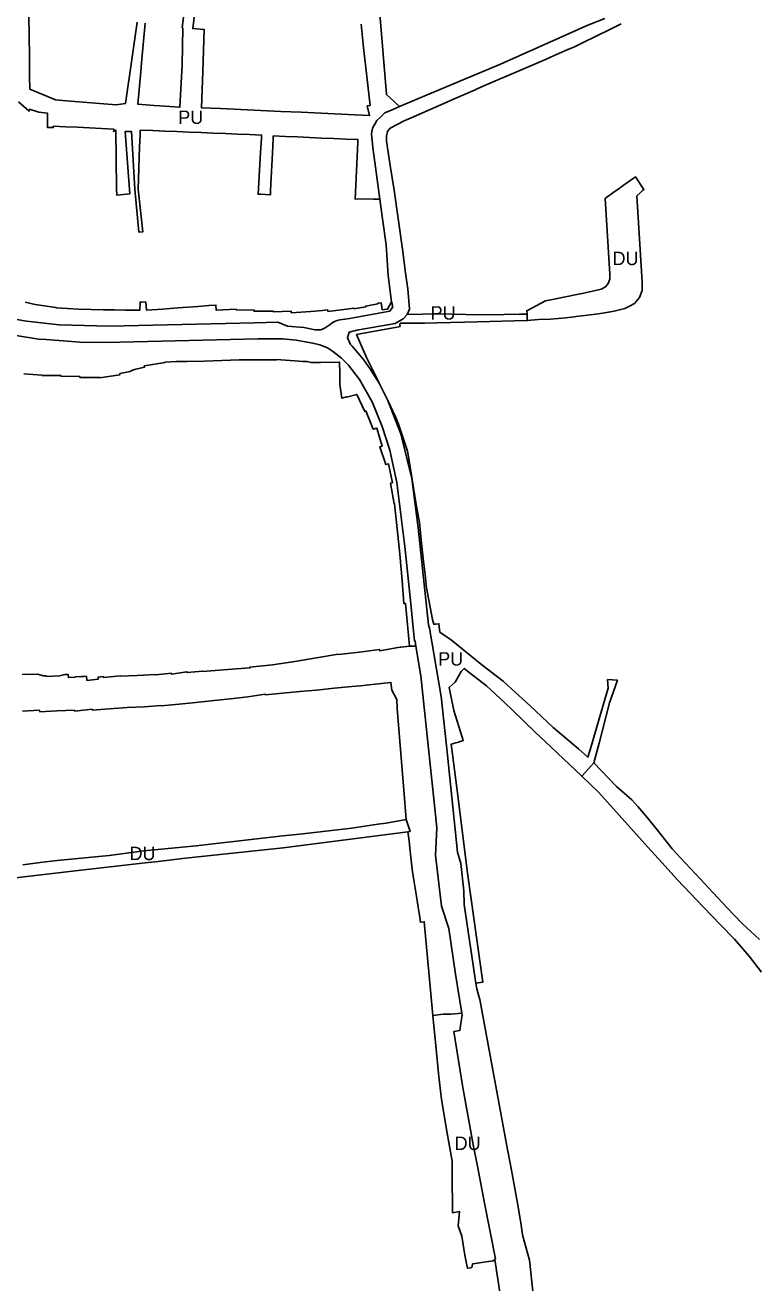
# Model space of a CAD drawing. Extents: x -521047 to -518054, y -1194945 to -1189555.
# Drawn here: x -519578 to -519036, y -1192557 to -1191621 of the extents above; entities that cross this region are included whole.
import ezdxf

# ---------------------------------------------------------------- set-up
doc = ezdxf.new("R2010")
doc.units = 0
for name, color, linetype in [('90310013', 7, 'Continuous'), ('90320013', 7, 'Continuous'), ('90450013', 7, 'Continuous')]:
    doc.layers.add(name, color=color, linetype=linetype)

msp = doc.modelspace()

# ---------------------------------------------------------------- linework, layer by layer
at = {"layer": '90310013'}
for points in [[(-519204.45, -1191836.01), (-519204.44, -1191840.74), (-519196.06, -1191840.09), (-519187.09, -1191839.8), (-519175.58, -1191838.62), (-519169.59, -1191838.01), (-519167.92, -1191837.84), (-519159.65, -1191836.74), (-519151.39, -1191835.65), (-519148.46, -1191835.26), (-519144.03, -1191834.48), (-519139.61, -1191833.71), (-519138.79, -1191833.51), (-519135.64, -1191832.73), (-519131.67, -1191831.75), (-519128.2, -1191830.17), (-519124.71, -1191827.98), (-519120.84, -1191823.71), (-519118.96, -1191818.4), (-519118.77, -1191812.14), (-519122.77, -1191748), (-519120.3, -1191745.63), (-519118.66, -1191744.06), (-519117.54, -1191743.31), (-519123.94, -1191733.72), (-519133.08, -1191740.22), (-519137.83, -1191743.66), (-519139.7, -1191745.02), (-519146.33, -1191749.83), (-519142.86, -1191806.26), (-519142.91, -1191809.87), (-519144.27, -1191813.29), (-519146.16, -1191815.78), (-519148.84, -1191817.18), (-519149.29, -1191817.29), (-519154.61, -1191818.54), (-519158.11, -1191819.36), (-519160.39, -1191819.9), (-519162.27, -1191820.28), (-519166.23, -1191821.08), (-519186.83, -1191825.25), (-519190.77, -1191826.05), (-519204.81, -1191833.46), (-519204.45, -1191836.01)], [(-519031.55, -1192301.49), (-519044.36, -1192289.47), (-519055.66, -1192277.84), (-519066.07, -1192266.75), (-519075.61, -1192256.39), (-519086.83, -1192244.28), (-519096.48, -1192233.98), (-519107.53, -1192220.17), (-519116.18, -1192209.51), (-519122, -1192202.34), (-519126.58, -1192197.51), (-519137.98, -1192187.52), (-519154.78, -1192169.89), (-519163.86, -1192179.96), (-519151.64, -1192191.56), (-519140.2, -1192204.21), (-519114.65, -1192232.63), (-519104.36, -1192244.08), (-519092.95, -1192256.78), (-519073.17, -1192277.32), (-519060.48, -1192290.5), (-519050.21, -1192301.17), (-519039.22, -1192313.8), (-519030.1, -1192325.84)], [(-519293.15, -1192221.23), (-519291.45, -1192221.01), (-519294.58, -1192212.21), (-519309.5, -1192214.8), (-519315.51, -1192215.67), (-519322.01, -1192216.62), (-519334.91, -1192218.48), (-519347.79, -1192219.96), (-519360.66, -1192221.43), (-519373.52, -1192222.91), (-519386.39, -1192224.39), (-519399.25, -1192225.86), (-519412.12, -1192227.34), (-519425.05, -1192228.82), (-519438.08, -1192230.21), (-519450.83, -1192231.68), (-519463.7, -1192232.94), (-519476.84, -1192234.28), (-519489.62, -1192235.55), (-519502.68, -1192237.21), (-519515.54, -1192238.85), (-519528.34, -1192240.22), (-519541.4, -1192241.29), (-519554.2, -1192242.66), (-519566.88, -1192244.15), (-519579.82, -1192245.81)], [(-519608.83, -1192258.36), (-519538.54, -1192250.02), (-519486.4, -1192244.11), (-519478.96, -1192243.26), (-519458.84, -1192240.98), (-519385.99, -1192233.14), (-519293.15, -1192221.23)], [(-519274.55, -1192357.98), (-519272, -1192385.55), (-519270.57, -1192401.05), (-519268.72, -1192416.34), (-519268.03, -1192422.01), (-519263.91, -1192445.66), (-519260.27, -1192466.51), (-519260.21, -1192475.38), (-519260.01, -1192504.83), (-519254.84, -1192503.78), (-519255.72, -1192514.6), (-519253.11, -1192522.25), (-519250.78, -1192536.34), (-519249.45, -1192543.81), (-519248.82, -1192546.17), (-519246.64, -1192545.7), (-519245.6, -1192545.49), (-519245.21, -1192542.95), (-519244.62, -1192542.72), (-519233.52, -1192541.1), (-519233.01, -1192541.03), (-519229.85, -1192540.57), (-519228.6, -1192539.54), (-519227.98, -1192539.02), (-519236.13, -1192497.59), (-519241.55, -1192470.11), (-519244.42, -1192455.6), (-519252.35, -1192411.52), (-519258.95, -1192369.88), (-519254.68, -1192369.2), (-519252.85, -1192357.24), (-519252.99, -1192356.37), (-519261, -1192356.96), (-519266.9, -1192356.98), (-519274.55, -1192357.98)]]:
    msp.add_lwpolyline(points, dxfattribs=at)
at = {"layer": '90320013'}
for points in [[(-519146.78, -1191615.88), (-519159.42, -1191620.98), (-519166.49, -1191624.15), (-519224.33, -1191649.88), (-519275.99, -1191671.57), (-519285.21, -1191675.48), (-519299.42, -1191681.52), (-519304.96, -1191683.89), (-519310.5, -1191686.25), (-519313.44, -1191689.04), (-519316.37, -1191691.83), (-519317.94, -1191694.71), (-519319.51, -1191697.58), (-519320.32, -1191701.75), (-519319.42, -1191711.86), (-519314, -1191750.49), (-519312.01, -1191764.97), (-519309.33, -1191784.48), (-519307.98, -1191807.22), (-519305.47, -1191826.76), (-519304.48, -1191830.56), (-519306.68, -1191833.7), (-519336.74, -1191839.11), (-519339.91, -1191839.62), (-519343.88, -1191840.31), (-519345.85, -1191840.71), (-519348.24, -1191841.65), (-519349.53, -1191842.44), (-519351.15, -1191843.6), (-519354.1, -1191845.76), (-519355.34, -1191846.53), (-519356.3, -1191846.96), (-519357.24, -1191847.32), (-519358.25, -1191847.56), (-519359.26, -1191847.67), (-519360.3, -1191847.76), (-519362.28, -1191847.68), (-519370.7, -1191846.05), (-519382.85, -1191844.82), (-519389.94, -1191842.05), (-519407.35, -1191842.43), (-519515.39, -1191844.88), (-519552.85, -1191843.86), (-519577.08, -1191841.18), (-519613.12, -1191835.08)], [(-519196.54, -1192598), (-519202.8, -1192540.04), (-519207.76, -1192522.22), (-519207.97, -1192520.87), (-519209.28, -1192512.28), (-519210.61, -1192503.54), (-519211.21, -1192500.28), (-519215.75, -1192475.83), (-519217.2, -1192467.98), (-519219.07, -1192457.81), (-519239.61, -1192346.18), (-519240.39, -1192343.49), (-519241.97, -1192338.08), (-519242.61, -1192333.86), (-519251.47, -1192275.39), (-519251.5, -1192265.15), (-519253.85, -1192244.78), (-519256.4, -1192236.48), (-519263.74, -1192164.26), (-519264.49, -1192157.17), (-519268.4, -1192120.48), (-519277.03, -1192069.78), (-519277.9, -1192067.2), (-519285.48, -1191994.93), (-519290.34, -1191958.3), (-519298.51, -1191925.1), (-519308.18, -1191900.28), (-519308.65, -1191899.33), (-519312.08, -1191892.37), (-519314.56, -1191887.33), (-519321, -1191877.16), (-519326.18, -1191869.79), (-519334.75, -1191859.93), (-519335.92, -1191858.58), (-519338.25, -1191853.54), (-519337.02, -1191849.51), (-519331.33, -1191847.96), (-519302.69, -1191842.95), (-519296.63, -1191839.59), (-519293.72, -1191836.26), (-519292.11, -1191832.38), (-519293.33, -1191817.07), (-519294.73, -1191807.26), (-519297.34, -1191787.75), (-519300.4, -1191764.9), (-519303.36, -1191743.79), (-519306.5, -1191725.42), (-519309.15, -1191707.14), (-519309.22, -1191703.48), (-519308.36, -1191700.15), (-519306.43, -1191697.63), (-519296.03, -1191692.09), (-519290.75, -1191689.81), (-519268.59, -1191680.16), (-519259.22, -1191676.08), (-519243.58, -1191669.19), (-519241.68, -1191668.36), (-519236.65, -1191666.15), (-519233.12, -1191664.6), (-519228.08, -1191662.46), (-519209.86, -1191654.59), (-519190.89, -1191646.39), (-519187.15, -1191644.77), (-519182.56, -1191642.78), (-519174.11, -1191639.14), (-519171.02, -1191637.8), (-519169.3, -1191636.96), (-519163.4, -1191634.08), (-519142.94, -1191624.08), (-519134.57, -1191619.98)], [(-519615.32, -1191846.99), (-519568.13, -1191854.57), (-519562.35, -1191854.98), (-519534.11, -1191856.98), (-519507.57, -1191856.77), (-519404.6, -1191854.48), (-519386.65, -1191854.46), (-519376.26, -1191855.26), (-519363.89, -1191857.47), (-519358.75, -1191858.92), (-519357.45, -1191859.28), (-519352.97, -1191861.17), (-519349.45, -1191863.46), (-519342.53, -1191868.86), (-519337.41, -1191873.89), (-519329.28, -1191884.7), (-519319.74, -1191901.29), (-519312.31, -1191919.57), (-519306.61, -1191937.19), (-519301.58, -1191961.19), (-519295.55, -1192009.01), (-519291.37, -1192049.22), (-519288.24, -1192079.39), (-519287.79, -1192079.36), (-519287.33, -1192083.23), (-519283.62, -1192105.11), (-519272.72, -1192208.59), (-519271.7, -1192218.25), (-519272.76, -1192238.61), (-519268.16, -1192276.7), (-519262.65, -1192293.24), (-519257.69, -1192327.13), (-519252.99, -1192356.37), (-519252.85, -1192357.24), (-519254.68, -1192369.2), (-519258.95, -1192369.88), (-519252.35, -1192411.52), (-519244.42, -1192455.6), (-519241.55, -1192470.11), (-519236.13, -1192497.59), (-519227.98, -1192539.02), (-519228.6, -1192539.54), (-519220.59, -1192591.78)]]:
    msp.add_lwpolyline(points, dxfattribs=at)
at = {"layer": '90450013'}
for points in [[(-519582.88, -1191677.87), (-519574.98, -1191684.89), (-519574.85, -1191683.54), (-519567.78, -1191685.68), (-519561.34, -1191686.44), (-519561.51, -1191696.96), (-519561.2, -1191697), (-519557.19, -1191697.14), (-519557.14, -1191696.09), (-519547.97, -1191696.52), (-519539.14, -1191696.94), (-519530.15, -1191697.36), (-519521.15, -1191697.78), (-519512.12, -1191698.2), (-519512.16, -1191699.05), (-519512.2, -1191700.05), (-519510.53, -1191699.1), (-519510.01, -1191742.32), (-519510.01, -1191742.53), (-519509.74, -1191747.47), (-519500.23, -1191746.39), (-519500.5, -1191743.31), (-519503.66, -1191700.1), (-519498.91, -1191700.04), (-519496.38, -1191742.87), (-519493.35, -1191774.96), (-519490.37, -1191774.64), (-519493.88, -1191742.97), (-519492.93, -1191711.67), (-519492.48, -1191702.17), (-519492.41, -1191700.03), (-519492.37, -1191699), (-519483.09, -1191699.39), (-519474.12, -1191699.76), (-519465.11, -1191700.14), (-519456.16, -1191700.51), (-519447.05, -1191700.89), (-519438.15, -1191701.26), (-519429.07, -1191701.64), (-519420.12, -1191702.01), (-519411.16, -1191702.39), (-519402.09, -1191702.77), (-519402.22, -1191705.03), (-519402.82, -1191715.71), (-519404.65, -1191746.7), (-519402.92, -1191746.8), (-519395.58, -1191747.25), (-519395.4, -1191744.56), (-519395.12, -1191739.06), (-519394.09, -1191716.18), (-519393.5, -1191705.59), (-519393.39, -1191703.3), (-519384.38, -1191703.7), (-519375.45, -1191704.1), (-519366.42, -1191704.5), (-519357.47, -1191704.9), (-519348.39, -1191705.3), (-519339.44, -1191705.7), (-519330.46, -1191706.1), (-519330.58, -1191708.44), (-519330.66, -1191712.9), (-519330.99, -1191719), (-519332.45, -1191750.42), (-519323.74, -1191750.23), (-519318.7, -1191750.36), (-519314, -1191750.49), (-519319.42, -1191711.86), (-519320.32, -1191701.75), (-519319.51, -1191697.58), (-519317.94, -1191694.71), (-519316.37, -1191691.83), (-519313.44, -1191689.04), (-519310.5, -1191686.25), (-519304.96, -1191683.89), (-519299.42, -1191681.52), (-519302.34, -1191678.73), (-519303.32, -1191677.79), (-519309.03, -1191672.4), (-519314.27, -1191609.51)], [(-519494.72, -1191618.59), (-519498.55, -1191646.53), (-519503.48, -1191679.19), (-519510.41, -1191680.24), (-519547.22, -1191677.19), (-519555.47, -1191676.51), (-519574.54, -1191668.43), (-519574.72, -1191659.19), (-519574.86, -1191643.99), (-519575.11, -1191628.65), (-519575.26, -1191613.61)], [(-519459.75, -1191610.77), (-519461.19, -1191622.93), (-519460.76, -1191622.98), (-519461.26, -1191650.45), (-519462.89, -1191681.97), (-519477.9, -1191680.94), (-519482.05, -1191680.66), (-519485.05, -1191680.45), (-519488.04, -1191680.25), (-519494.16, -1191679.83), (-519492, -1191655.7), (-519491.4, -1191649.03), (-519488.74, -1191619.37)], [(-519327.99, -1191620.23), (-519326.26, -1191637.52), (-519321.31, -1191680.65), (-519323.47, -1191680.99), (-519321.76, -1191688.15), (-519332.65, -1191687.64), (-519357.86, -1191686.47), (-519372.73, -1191685.78), (-519387.89, -1191685.08), (-519402.72, -1191684.39), (-519417.54, -1191683.7), (-519432.73, -1191682.99), (-519446.94, -1191682.33), (-519445.77, -1191655.52), (-519444.85, -1191624.06), (-519453.36, -1191623.48), (-519451.82, -1191611.01)], [(-519613.12, -1191835.08), (-519577.08, -1191841.18), (-519552.85, -1191843.86), (-519515.39, -1191844.88), (-519407.35, -1191842.43), (-519389.94, -1191842.05), (-519382.85, -1191844.82), (-519370.7, -1191846.05), (-519362.28, -1191847.68), (-519360.3, -1191847.76), (-519359.26, -1191847.67), (-519358.25, -1191847.56), (-519357.24, -1191847.32), (-519356.3, -1191846.96), (-519355.34, -1191846.53), (-519354.1, -1191845.76), (-519351.15, -1191843.6), (-519349.53, -1191842.44), (-519348.24, -1191841.65), (-519345.85, -1191840.71), (-519343.88, -1191840.31), (-519339.91, -1191839.62), (-519336.74, -1191839.11), (-519306.68, -1191833.7), (-519304.48, -1191830.56), (-519305.47, -1191826.76), (-519308.4, -1191832.41), (-519310.61, -1191832.63), (-519312.28, -1191832.79), (-519313.18, -1191827.54), (-519315.59, -1191827.82), (-519315.48, -1191828.28), (-519324.53, -1191830.01), (-519324.45, -1191830.5), (-519333.34, -1191831.93), (-519333.42, -1191831.44), (-519338.88, -1191832.32), (-519352.79, -1191833.93), (-519352.88, -1191832.88), (-519356.74, -1191833.24), (-519365.51, -1191834.06), (-519379.97, -1191834.93), (-519380.1, -1191833.68), (-519393.48, -1191834.29), (-519393.49, -1191833.69), (-519407.71, -1191833.84), (-519407.7, -1191832.91), (-519420.98, -1191832.84), (-519421.02, -1191832.26), (-519435.94, -1191833.01), (-519436.09, -1191829.27), (-519441.48, -1191829.65), (-519449.66, -1191830.24), (-519464.41, -1191831.37), (-519475.81, -1191832.25), (-519487.73, -1191833.14), (-519488.25, -1191826.86), (-519491.26, -1191827.06), (-519492.58, -1191827.06), (-519492.61, -1191832.95), (-519503.31, -1191832.91), (-519511.58, -1191832.89), (-519519.67, -1191832.83), (-519528.86, -1191832.47), (-519538.3, -1191832.18), (-519546.64, -1191831.68), (-519546.66, -1191831.88), (-519555.2, -1191831.22), (-519555.18, -1191831.02), (-519570.61, -1191828.79), (-519578.11, -1191827)], [(-519204.45, -1191836.01), (-519210.21, -1191836.07), (-519221.64, -1191836.2), (-519239.08, -1191836.39), (-519250.03, -1191836.27), (-519271.23, -1191835.76), (-519293.72, -1191836.26), (-519296.63, -1191839.59), (-519302.69, -1191842.95), (-519331.33, -1191847.96), (-519337.02, -1191849.51), (-519338.25, -1191853.54), (-519335.92, -1191858.58), (-519334.75, -1191859.93), (-519326.18, -1191869.79), (-519321, -1191877.16), (-519314.56, -1191887.33), (-519316.81, -1191882.74), (-519319.78, -1191876.69), (-519323.98, -1191868.14), (-519331.39, -1191851.19), (-519324.73, -1191849.97), (-519313.73, -1191847.82), (-519301.58, -1191845.62), (-519299.01, -1191845.15), (-519299.34, -1191843.92), (-519298.91, -1191842.75), (-519294.9, -1191842.75), (-519280.5, -1191842.73), (-519271.64, -1191842.5), (-519250.93, -1191841.96), (-519241.47, -1191841.71), (-519232.17, -1191841.47), (-519214.23, -1191841), (-519204.44, -1191840.74), (-519204.45, -1191836.01)], [(-519287.33, -1192083.23), (-519287.79, -1192079.36), (-519288.24, -1192079.39), (-519291.37, -1192049.22), (-519295.55, -1192009.01), (-519301.58, -1191961.19), (-519306.61, -1191937.19), (-519312.31, -1191919.57), (-519319.74, -1191901.29), (-519329.28, -1191884.7), (-519337.41, -1191873.89), (-519342.53, -1191868.86), (-519349.45, -1191863.46), (-519352.97, -1191861.17), (-519357.45, -1191859.28), (-519358.75, -1191858.92), (-519363.89, -1191857.47), (-519376.26, -1191855.26), (-519386.65, -1191854.46), (-519404.6, -1191854.48), (-519507.57, -1191856.77), (-519534.11, -1191856.98), (-519562.35, -1191854.98), (-519568.13, -1191854.57), (-519615.32, -1191846.99)], [(-519579, -1191880.45), (-519565.6, -1191881.32), (-519565.6, -1191881.62), (-519551.33, -1191881.65), (-519551.38, -1191882.16), (-519537.47, -1191882.37), (-519537.48, -1191883.07), (-519522.63, -1191883.08), (-519522.7, -1191883.32), (-519507.59, -1191881.06), (-519507.71, -1191880.25), (-519499.82, -1191878.64), (-519498.15, -1191877.65), (-519495.63, -1191877.04), (-519489.27, -1191875.52), (-519489.47, -1191874.45), (-519473.93, -1191871.93), (-519473.94, -1191871.63), (-519465.7, -1191871.14), (-519457.52, -1191871.31), (-519444.72, -1191870.92), (-519431.79, -1191870.52), (-519418.67, -1191870.09), (-519411.36, -1191869.95), (-519404.99, -1191869.94), (-519391.15, -1191870.1), (-519391.14, -1191869.66), (-519377.4, -1191870.85), (-519371.38, -1191871.16), (-519368.3, -1191871.35), (-519365.28, -1191872.04), (-519364.04, -1191872.03), (-519358.14, -1191871.97), (-519344.09, -1191871.71), (-519343.92, -1191880.01), (-519343.76, -1191888.27), (-519342.36, -1191898.61), (-519339.03, -1191897.65), (-519338.96, -1191897.89), (-519331.25, -1191895.74), (-519325.36, -1191908.39), (-519324.57, -1191908.03), (-519319.02, -1191921.61), (-519316.26, -1191920.8), (-519312.4, -1191934.18), (-519314.16, -1191934.69), (-519309.62, -1191947.92), (-519307.59, -1191947.47), (-519304.75, -1191961.44), (-519306.1, -1191961.74), (-519303.38, -1191977.15), (-519303.08, -1191977.09), (-519301.8, -1191991.05), (-519300.25, -1192005.11), (-519299.18, -1192014.58), (-519297.61, -1192034.3), (-519296.24, -1192051.47), (-519294.92, -1192051.31), (-519292.11, -1192083.19), (-519287.33, -1192083.23)], [(-519144.75, -1192107.98), (-519144.18, -1192114.28), (-519150.91, -1192137.25), (-519157.63, -1192160.22), (-519159.22, -1192165.64), (-519166.26, -1192159.46), (-519185.23, -1192143.73), (-519202.6, -1192127.31), (-519213.07, -1192117.6), (-519222.29, -1192109.06), (-519238.16, -1192097.11), (-519260.74, -1192078.72), (-519269.35, -1192072.68), (-519270.14, -1192066.39), (-519272.62, -1192066.65), (-519274.02, -1192066.8), (-519275, -1192063.24), (-519279.42, -1192039.81), (-519280.49, -1192029.76), (-519281.56, -1192019.78), (-519282.99, -1192006.36), (-519284.71, -1191991.14), (-519286.95, -1191977.61), (-519289.23, -1191963.78), (-519291.32, -1191951.11), (-519293.5, -1191937.93), (-519300.48, -1191917.22), (-519302.36, -1191912.5), (-519308.18, -1191900.28), (-519298.51, -1191925.1), (-519290.34, -1191958.3), (-519285.48, -1191994.93), (-519277.9, -1192067.2), (-519277.03, -1192069.78), (-519268.4, -1192120.48), (-519264.49, -1192157.17), (-519263.74, -1192164.26), (-519256.4, -1192236.48), (-519253.85, -1192244.78), (-519251.5, -1192265.15), (-519251.47, -1192275.39), (-519242.61, -1192333.86), (-519237.4, -1192333.12), (-519248.6, -1192253.76), (-519256.86, -1192188.66), (-519260.98, -1192156.12), (-519257.52, -1192155.08), (-519255.52, -1192154.48), (-519253.52, -1192153.88), (-519252.06, -1192153.44), (-519252.86, -1192150.95), (-519259.12, -1192130.89), (-519262.54, -1192113.84), (-519258.05, -1192109.92), (-519253.56, -1192102.06), (-519251.34, -1192099.69), (-519246.52, -1192103.57), (-519234.78, -1192112.54), (-519221.44, -1192124.92), (-519215.42, -1192130.75), (-519198.53, -1192147.1), (-519186.72, -1192158.24), (-519163.86, -1192179.96), (-519154.78, -1192169.89), (-519151, -1192155.37), (-519143.17, -1192125.35), (-519137.32, -1192108.5), (-519144.75, -1192107.98)], [(-519296.37, -1192190.24), (-519294.58, -1192212.21), (-519291.45, -1192221.01), (-519293.15, -1192221.23), (-519292.39, -1192228.11), (-519291.8, -1192233.4), (-519290, -1192248.98), (-519288.95, -1192255.73), (-519287.31, -1192266.22), (-519284.84, -1192282.04), (-519284.43, -1192284.69), (-519283.96, -1192288.62), (-519281.07, -1192288.24), (-519274.55, -1192357.98), (-519266.9, -1192356.98), (-519261, -1192356.96), (-519252.99, -1192356.37), (-519257.69, -1192327.13), (-519262.65, -1192293.24), (-519268.16, -1192276.7), (-519272.76, -1192238.61), (-519271.7, -1192218.25), (-519272.72, -1192208.59), (-519283.62, -1192105.11), (-519287.33, -1192083.23), (-519292.11, -1192083.19), (-519294.12, -1192083.41), (-519294.21, -1192083.42), (-519296.26, -1192083.64), (-519298.59, -1192083.9), (-519298.96, -1192083.94), (-519301.98, -1192084.29), (-519314.17, -1192086.57), (-519314.26, -1192085.63), (-519329.17, -1192087.46), (-519344.94, -1192089.4), (-519345.03, -1192089.14), (-519361.23, -1192091.78), (-519377.32, -1192094.41), (-519393.9, -1192097.05), (-519410.86, -1192098.74), (-519410.81, -1192099.26), (-519427.32, -1192100.48), (-519445.96, -1192101.9), (-519446, -1192101.62), (-519457.55, -1192102.74), (-519457.69, -1192102.09), (-519469.05, -1192103.98), (-519469.17, -1192103.23), (-519480.91, -1192104.52), (-519480.92, -1192104.22), (-519494.66, -1192104.9), (-519507.29, -1192105.47), (-519507.29, -1192105.23), (-519519.64, -1192106.53), (-519519.76, -1192105.66), (-519523.82, -1192106.11), (-519523.65, -1192107.63), (-519532.12, -1192108.6), (-519532.48, -1192105.44), (-519534.34, -1192105.58), (-519536.21, -1192105.72), (-519540.76, -1192106.01), (-519540.75, -1192106.11), (-519545.9, -1192106.44), (-519546.15, -1192104.08), (-519548.44, -1192104.29), (-519552.49, -1192105.08), (-519562.34, -1192105.68), (-519562.37, -1192105.19), (-519564.63, -1192105.29), (-519568.5, -1192103.84), (-519580.3, -1192104.25)], [(-519580.06, -1192131.4), (-519567.37, -1192130.77), (-519567.24, -1192131.88), (-519554.39, -1192131.3), (-519541.15, -1192130.8), (-519541.1, -1192131.39), (-519528.2, -1192130.1), (-519528.16, -1192130.64), (-519515.25, -1192129.68), (-519502.16, -1192128.8), (-519489.38, -1192128.18), (-519476.73, -1192127.34), (-519476.72, -1192127.47), (-519463.48, -1192126.37), (-519450.91, -1192125.01), (-519437.49, -1192123.59), (-519425.19, -1192122.19), (-519412.26, -1192120.71), (-519399.38, -1192118.93), (-519399.31, -1192119.24), (-519386.66, -1192118.08), (-519373.62, -1192116.82), (-519361.26, -1192115.76), (-519347.97, -1192114.43), (-519335.06, -1192113.18), (-519328.43, -1192112.58), (-519322.01, -1192111.91), (-519305.9, -1192110.04), (-519305.27, -1192115.84), (-519301.51, -1192122.77), (-519301.09, -1192129.57), (-519300.61, -1192135.79), (-519296.37, -1192190.24)]]:
    msp.add_lwpolyline(points, dxfattribs=at)

# ---------------------------------------------------------------- texts
at = {"layer": '90310013'}
for rotation, p in [(360, (-519140.92, -1191799.52)), (0, (-519500.37, -1192242.36)), (0, (-519258.42, -1192458.1))]:
    msp.add_text('DU', height=10, rotation=rotation, dxfattribs=at).set_placement(p)
at = {"layer": '90450013'}
for rotation, p in [(360, (-519464.12, -1191694.45)), (360, (-519276.32, -1191840.08)), (0, (-519270.67, -1192097.58))]:
    msp.add_text('PU', height=10, rotation=rotation, dxfattribs=at).set_placement(p)

doc.saveas('drawing.dxf')
